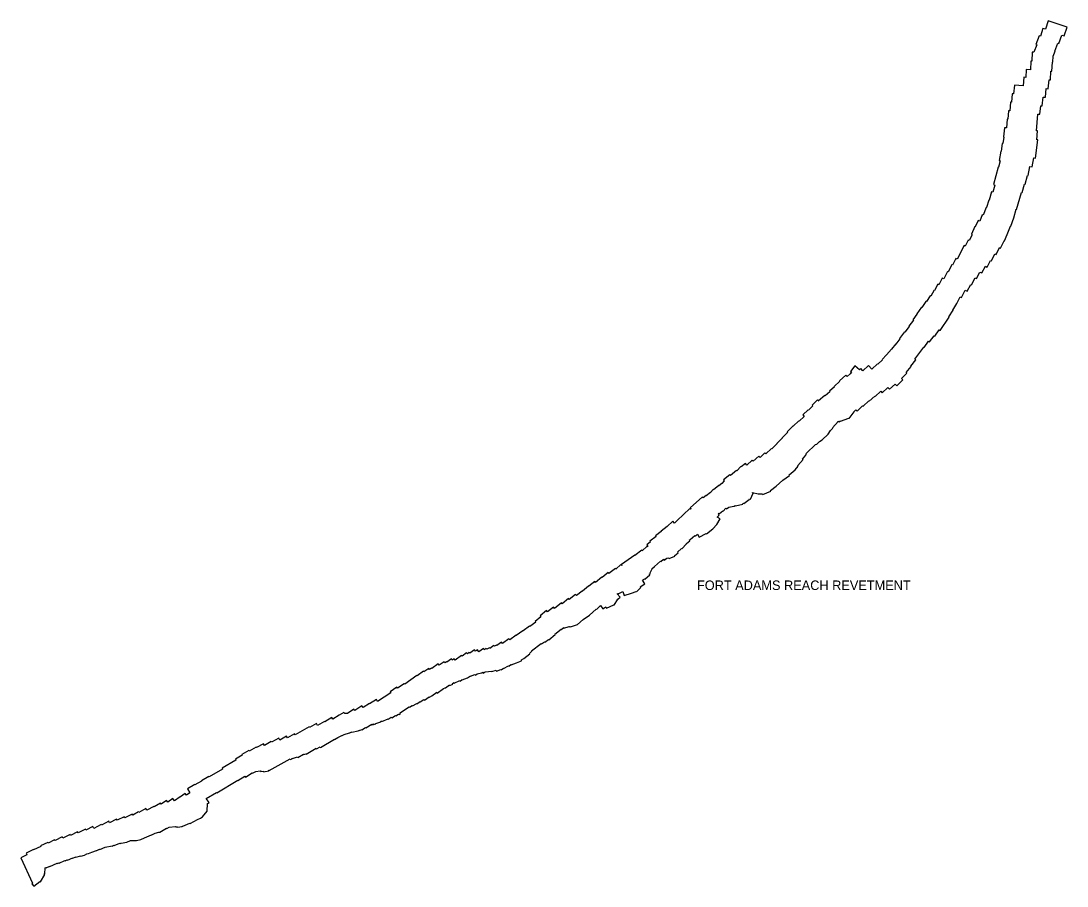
# Model space of a CAD drawing. Extents: x 2650582 to 3923188, y 277893 to 989177.
# Drawn here: x 3192684 to 3210259, y 910761 to 925302 of the extents above; entities that cross this region are included whole.
import ezdxf

# ---------------------------------------------------------------- set-up
doc = ezdxf.new("R2010")
doc.units = 0
doc.layers.add('Level 3', color=7, linetype='Continuous')

msp = doc.modelspace()

# ---------------------------------------------------------------- linework, layer by layer
at = {"layer": 'Level 3'}
for points in [[(3209762, 923454), (3209745, 923456), (3209768, 923736), (3209803, 923733), (3209816, 923877), (3209843, 923874), (3209855, 924023), (3209896, 924019), (3209910, 924165), (3209943, 924162), (3209956, 924314), (3209981, 924314), (3209987, 924459), (3210005, 924459), (3210012, 924608), (3210021, 924609), (3210025, 924708), (3210060, 924792), (3210055, 924794), (3210106, 924929), (3210123, 924923), (3210170, 925063), (3210212, 925050), (3210259, 925198), (3209939, 925302), (3209894, 925161), (3209853, 925174), (3209810, 925045), (3209792, 925052), (3209736, 924907), (3209749, 924901), (3209700, 924776), (3209674, 924776), (3209668, 924627), (3209650, 924628), (3209644, 924482), (3209572, 924483), (3209566, 924353), (3209535, 924355), (3209524, 924209), (3209373, 924222), (3209361, 924075), (3209334, 924077), (3209323, 923934), (3209308, 923935), (3209296, 923791), (3209274, 923793)], [(3209274, 923793), (3209261, 923650), (3209251, 923651), (3209239, 923507), (3209208, 923508), (3209193, 923352), (3209196, 923351), (3209182, 923242), (3209171, 923242), (3209150, 923112), (3209144, 923112), (3209116, 922956), (3209133, 922952), (3209107, 922842), (3209099, 922843), (3209022, 922550), (3209047, 922543), (3209010, 922422), (3208992, 922427), (3208948, 922288), (3208945, 922289), (3208906, 922164), (3208897, 922167), (3208850, 922035), (3208833, 922041), (3208792, 921937), (3208764, 921947), (3208717, 921843), (3208712, 921845), (3208652, 921716), (3208665, 921709), (3208616, 921609), (3208596, 921618), (3208548, 921518), (3208530, 921528), (3208410, 921300), (3208393, 921307), (3208336, 921195), (3208323, 921201), (3208262, 921085), (3208257, 921087), (3208251, 921090), (3208186, 920966)], [(3208548, 920774), (3208578, 920758), (3208640, 920874), (3208653, 920867), (3208714, 920983), (3208737, 920972), (3208795, 921081), (3208826, 921066), (3208887, 921179), (3208914, 921166), (3208973, 921278), (3208992, 921270), (3209048, 921385), (3209068, 921376), (3209125, 921493), (3209142, 921485), (3209200, 921607), (3209207, 921604), (3209253, 921711), (3209307, 921853), (3209313, 921851), (3209367, 921994), (3209365, 921994), (3209406, 922136), (3209408, 922135), (3209492, 922421), (3209504, 922418), (3209542, 922560), (3209555, 922557), (3209593, 922706), (3209603, 922704), (3209636, 922853), (3209671, 922848), (3209701, 923000), (3209730, 922995), (3209768, 923302), (3209749, 923306), (3209762, 923454)], [(3208186, 920966), (3208163, 920980), (3208102, 920868), (3208088, 920875), (3208034, 920773), (3208027, 920777), (3207968, 920676), (3207959, 920682), (3207897, 920585), (3207889, 920589), (3207818, 920486), (3207812, 920490), (3207733, 920377), (3207736, 920375), (3207668, 920279), (3207679, 920271), (3207602, 920169), (3207606, 920166), (3207534, 920073), (3207530, 920076), (3207446, 919964), (3207450, 919960), (3207381, 919870), (3207380, 919872), (3207311, 919785), (3207309, 919787), (3207225, 919690), (3207226, 919689), (3207153, 919613), (3207158, 919607), (3207080, 919534), (3207075, 919538), (3206979, 919447), (3206923, 919508), (3206828, 919421), (3206792, 919458), (3206773, 919440), (3206691, 919503), (3206622, 919411), (3206637, 919398), (3206615, 919370), (3206566, 919324), (3206542, 919348), (3206438, 919253), (3206444, 919246), (3206346, 919159), (3206351, 919153), (3206268, 919078), (3206276, 919068), (3206195, 919000), (3206188, 919008), (3206081, 918918), (3206088, 918909), (3206067, 918931)], [(3206677, 918734), (3206710, 918764), (3206730, 918745), (3206823, 918834), (3206833, 918825), (3206929, 918915), (3206936, 918909), (3207029, 918995), (3207034, 918990), (3207130, 919078), (3207155, 919051), (3207250, 919138), (3207276, 919111), (3207370, 919198), (3207398, 919170), (3207499, 919269), (3207479, 919290), (3207568, 919382), (3207557, 919394), (3207642, 919493), (3207633, 919499), (3207717, 919606), (3207701, 919617), (3207850, 919819), (3207856, 919815), (3207931, 919919), (3207947, 919908), (3208025, 920010), (3208035, 920003), (3208111, 920109), (3208127, 920101), (3208280, 920325), (3208275, 920328), (3208347, 920440), (3208342, 920443), (3208406, 920554), (3208408, 920553), (3208464, 920662), (3208487, 920651), (3208548, 920774)], [(3206067, 918931), (3205978, 918845), (3205990, 918832), (3205915, 918760), (3205910, 918765), (3205821, 918679), (3205843, 918656), (3205757, 918573), (3205750, 918580), (3205656, 918490), (3205654, 918491), (3205554, 918394), (3205564, 918384), (3205470, 918294), (3205475, 918289), (3205382, 918198), (3205385, 918194), (3205299, 918111), (3205292, 918118), (3205199, 918028), (3205184, 918042), (3205103, 917964), (3205083, 917985), (3204985, 917900), (3204970, 917917), (3204878, 917837), (3204856, 917865), (3204784, 917806)], [(3204972, 917374), (3205068, 917356), (3205145, 917351), (3205147, 917345), (3205280, 917401), (3205279, 917409), (3205373, 917482), (3205486, 917581), (3205595, 917664), (3205589, 917673), (3205691, 917758), (3205742, 917821), (3205735, 917827), (3205824, 917933), (3205817, 917939), (3205872, 918004), (3205882, 918036), (3206035, 918185), (3206053, 918191), (3206098, 918235), (3206144, 918262), (3206246, 918356), (3206243, 918359), (3206283, 918419), (3206324, 918460), (3206321, 918463), (3206414, 918567), (3206415, 918575), (3206427, 918562), (3206452, 918583), (3206455, 918577), (3206590, 918627), (3206601, 918620), (3206680, 918732), (3206677, 918734)], [(3204784, 917806), (3204777, 917812), (3204713, 917741), (3204708, 917747), (3204605, 917659), (3204593, 917674), (3204486, 917589), (3204499, 917571), (3204460, 917527), (3204410, 917488), (3204406, 917493), (3204317, 917421), (3204313, 917424), (3204269, 917375), (3204198, 917321), (3204195, 917326), (3204143, 917285), (3204129, 917300), (3204034, 917211), (3204031, 917215), (3203928, 917119), (3203942, 917105), (3203931, 917094), (3203919, 917105), (3203711, 916903), (3203683, 916877), (3203664, 916861), (3203636, 916893), (3203538, 916807), (3203438, 916726), (3203441, 916722), (3203345, 916650), (3203356, 916635), (3203252, 916557), (3203260, 916547), (3203197, 916499), (3203218, 916468), (3203213, 916464), (3203202, 916474), (3203120, 916398), (3203116, 916404), (3202999, 916319), (3202995, 916324), (3202772, 916165), (3202781, 916153)], [(3203479, 916257), (3203493, 916237), (3203537, 916270), (3203571, 916279), (3203576, 916268), (3203671, 916305), (3203667, 916318), (3203723, 916364), (3203717, 916372), (3203783, 916434), (3203788, 916430), (3203867, 916514), (3203864, 916516), (3203921, 916566), (3203913, 916574), (3203926, 916587), (3204003, 916654), (3204015, 916640), (3204053, 916674), (3204076, 916628), (3204198, 916686), (3204200, 916683), (3204308, 916766), (3204310, 916765), (3204374, 916836), (3204433, 916932), (3204383, 916963), (3204415, 916993), (3204401, 917009), (3204417, 917028), (3204421, 917025), (3204474, 917070), (3204484, 917063), (3204528, 917114), (3204537, 917102), (3204576, 917130), (3204663, 917148), (3204665, 917146), (3204684, 917160), (3204687, 917150), (3204812, 917181), (3204812, 917186), (3204823, 917195), (3204828, 917190), (3204920, 917256), (3204918, 917259), (3204925, 917269), (3204939, 917263), (3204986, 917362), (3204972, 917371), (3204972, 917374)], [(3201660, 914990), (3201656, 914996), (3201759, 915077), (3201761, 915074), (3201804, 915106), (3201807, 915097), (3201893, 915123), (3201899, 915117), (3201912, 915126), (3201914, 915120), (3202036, 915159), (3202131, 915239), (3202234, 915315), (3202236, 915313), (3202347, 915413), (3202351, 915408), (3202418, 915474), (3202460, 915419), (3202510, 915456), (3202519, 915434), (3202645, 915487), (3202651, 915484), (3202712, 915585), (3202749, 915614), (3202700, 915675), (3202710, 915680), (3202715, 915671), (3202798, 915712), (3202818, 915645), (3202942, 915684), (3202943, 915682), (3203019, 915712), (3203025, 915706), (3203097, 915778), (3203087, 915789), (3203167, 915843), (3203124, 915905), (3203162, 915925), (3203167, 915920), (3203247, 915993), (3203241, 916001), (3203258, 916017), (3203253, 916023), (3203287, 916091), (3203284, 916093), (3203327, 916133), (3203330, 916130), (3203429, 916223), (3203432, 916218), (3203479, 916257)], [(3202781, 916153), (3202778, 916149), (3202762, 916166), (3202679, 916090), (3202671, 916101), (3202563, 916015), (3202550, 916031), (3202447, 915945), (3202443, 915952), (3202339, 915866), (3202326, 915882), (3202222, 915799), (3202220, 915800), (3202117, 915717), (3202113, 915720), (3202018, 915645), (3202003, 915663), (3201895, 915577), (3201883, 915592), (3201774, 915505), (3201763, 915519), (3201648, 915426), (3201629, 915448), (3201532, 915369), (3201514, 915390), (3201407, 915303), (3201418, 915288), (3201323, 915210), (3201332, 915197), (3201231, 915125), (3201228, 915128), (3201119, 915050), (3201116, 915053), (3201006, 914974), (3201003, 914978), (3200895, 914902), (3200883, 914917), (3200775, 914838), (3200758, 914861), (3200679, 914804)], [(3198975, 913628), (3198980, 913622), (3199025, 913653), (3199032, 913643), (3199060, 913663), (3199054, 913672), (3199093, 913700), (3199094, 913698), (3199207, 913772), (3199210, 913767), (3199258, 913796), (3199261, 913790), (3199333, 913827), (3199335, 913824), (3199390, 913861), (3199393, 913857), (3199454, 913894), (3199462, 913883), (3199543, 913941), (3199547, 913935), (3199586, 913957), (3199669, 914018), (3199676, 914006), (3199782, 914084), (3199785, 914080), (3199812, 914093), (3199814, 914091), (3199886, 914142), (3199892, 914131), (3199938, 914157), (3199935, 914164), (3199960, 914181), (3199965, 914171), (3200055, 914216), (3200062, 914206), (3200097, 914231), (3200099, 914227), (3200184, 914263), (3200187, 914260), (3200234, 914294), (3200238, 914288), (3200310, 914319), (3200320, 914305), (3200349, 914326), (3200421, 914343), (3200422, 914341), (3200441, 914355), (3200451, 914341), (3200482, 914363), (3200596, 914374), (3200597, 914367), (3200670, 914389), (3200675, 914375), (3200747, 914399), (3200750, 914395), (3200789, 914425), (3200793, 914419), (3200873, 914465), (3200879, 914457), (3200917, 914485), (3200919, 914479), (3201009, 914511), (3201008, 914512), (3201095, 914548), (3201091, 914561), (3201131, 914584), (3201130, 914588), (3201132, 914586), (3201232, 914663), (3201228, 914668), (3201266, 914709), (3201260, 914714), (3201426, 914840), (3201432, 914832), (3201479, 914866), (3201483, 914861), (3201546, 914908), (3201550, 914902), (3201660, 914990)], [(3200679, 914804), (3200676, 914809), (3200641, 914791), (3200630, 914805), (3200560, 914754), (3200555, 914763), (3200512, 914741), (3200501, 914756), (3200468, 914732), (3200453, 914753), (3200377, 914698), (3200353, 914732), (3200320, 914710), (3200305, 914730), (3200228, 914673), (3200217, 914687), (3200185, 914664), (3200171, 914683), (3200094, 914627), (3200086, 914638), (3199979, 914558), (3199960, 914582), (3199929, 914559), (3199915, 914578), (3199840, 914524), (3199835, 914530), (3199810, 914513), (3199795, 914532), (3199713, 914473), (3199695, 914495), (3199589, 914418), (3199584, 914424), (3199549, 914399), (3199535, 914420), (3199453, 914361), (3199446, 914371), (3199339, 914297), (3199336, 914302), (3199131, 914153), (3199124, 914162), (3199011, 914090), (3199001, 914104), (3198886, 914027), (3198899, 914007), (3198677, 913864)], [(3198677, 913864), (3198655, 913897), (3198542, 913825), (3198538, 913830), (3198431, 913761), (3198411, 913791), (3198293, 913714), (3198279, 913732), (3198168, 913660), (3198123, 913660), (3198109, 913680), (3198031, 913631), (3198028, 913635), (3197925, 913568), (3197906, 913595), (3197788, 913524), (3197786, 913528), (3197667, 913461), (3197648, 913493), (3197533, 913426), (3197526, 913437), (3197292, 913303), (3197282, 913321), (3197163, 913254), (3197147, 913282), (3197032, 913216), (3197014, 913248), (3196895, 913180), (3196889, 913190), (3196776, 913126), (3196760, 913154), (3196642, 913089), (3196637, 913097), (3196519, 913030), (3196513, 913039), (3196395, 912971), (3196402, 912959), (3196286, 912892), (3196294, 912878), (3196062, 912744), (3196072, 912727), (3195848, 912597), (3195843, 912605), (3195715, 912530), (3195718, 912524), (3195608, 912460), (3195604, 912466), (3195482, 912396), (3195519, 912330)], [(3195797, 912230), (3195971, 912334), (3195974, 912329), (3196327, 912540), (3196330, 912537), (3196446, 912606), (3196454, 912593), (3196569, 912662), (3196573, 912656), (3196629, 912686), (3196702, 912696), (3196705, 912691), (3196715, 912696), (3196717, 912686), (3196758, 912694), (3196760, 912683), (3196848, 912700), (3196848, 912708), (3196853, 912708), (3196857, 912701), (3197206, 912901), (3197211, 912891), (3197244, 912910), (3197246, 912905), (3197330, 912932), (3197338, 912922), (3197432, 912976), (3197434, 912971), (3197473, 912985), (3197475, 912980), (3197643, 913077), (3197648, 913068), (3197711, 913099), (3197715, 913092), (3197952, 913228), (3197953, 913225), (3198007, 913256), (3198007, 913257), (3198075, 913294), (3198079, 913289), (3198112, 913309), (3198113, 913307), (3198206, 913339), (3198210, 913334), (3198242, 913354), (3198245, 913347), (3198347, 913368), (3198348, 913372), (3198351, 913369), (3198371, 913382), (3198374, 913375), (3198410, 913390), (3198411, 913388), (3198472, 913424), (3198476, 913418), (3198577, 913480), (3198581, 913471), (3198599, 913477), (3198598, 913482), (3198606, 913487), (3198609, 913479), (3198649, 913490), (3198649, 913494), (3198731, 913522), (3198730, 913527), (3198744, 913536), (3198748, 913527), (3198852, 913569), (3198854, 913566), (3198906, 913602), (3198914, 913590), (3198975, 913628)], [(3195519, 912330), (3195468, 912289), (3195443, 912317), (3195362, 912258), (3195358, 912262), (3195262, 912193), (3195234, 912231), (3195150, 912172), (3195131, 912198), (3195038, 912137), (3195026, 912156), (3194921, 912093), (3194917, 912099), (3194801, 912034), (3194784, 912064), (3194666, 911997), (3194660, 912006), (3194562, 911951), (3194551, 911972), (3194430, 911909), (3194421, 911925), (3194301, 911869), (3194292, 911886), (3194173, 911824), (3194159, 911849), (3194035, 911785), (3194030, 911793), (3193911, 911729), (3193894, 911760), (3193775, 911698), (3193767, 911715), (3193646, 911653), (3193635, 911672), (3193517, 911612), (3193509, 911628), (3193388, 911567), (3193377, 911587), (3193257, 911526), (3193250, 911539), (3193143, 911484), (3193138, 911494), (3193013, 911437), (3193016, 911428), (3192896, 911370), (3192894, 911373), (3192773, 911315)], [(3193091, 911069), (3193105, 911075), (3193107, 911070), (3193169, 911096), (3193172, 911090), (3193294, 911147), (3193297, 911141), (3193322, 911151), (3193324, 911146), (3193424, 911190), (3193426, 911187), (3193461, 911204), (3193464, 911198), (3193555, 911236), (3193557, 911232), (3193605, 911253), (3193606, 911249), (3193692, 911269), (3193693, 911265), (3193750, 911283), (3193791, 911302), (3193820, 911308), (3193873, 911333), (3193875, 911329), (3193955, 911361), (3193957, 911356), (3194006, 911379), (3194008, 911375), (3194100, 911412), (3194214, 911437), (3194216, 911433), (3194248, 911446), (3194249, 911443), (3194345, 911482), (3194349, 911475), (3194369, 911482), (3194461, 911497), (3194526, 911526), (3194624, 911529), (3194624, 911528), (3194697, 911541), (3194762, 911570), (3194760, 911574), (3194880, 911624), (3194882, 911621), (3194937, 911651), (3194998, 911665), (3195018, 911666), (3195132, 911733), (3195135, 911728), (3195177, 911750), (3195283, 911764), (3195285, 911757), (3195313, 911759), (3195314, 911752), (3195394, 911761), (3195394, 911766), (3195405, 911766), (3195524, 911819), (3195526, 911815), (3195652, 911882), (3195653, 911879), (3195699, 911905), (3195732, 911927), (3195815, 912022), (3195821, 912147), (3195845, 912167), (3195797, 912230)], [(3192773, 911315), (3192784, 911292), (3192782, 911291), (3192785, 911284), (3192684, 911238), (3192879, 910810), (3192868, 910801), (3192900, 910761), (3193003, 910839), (3193015, 910830), (3193087, 910954), (3193070, 910964), (3193085, 910964), (3193091, 911069)]]:
    msp.add_lwpolyline(points, dxfattribs=at)

# ---------------------------------------------------------------- texts
msp.add_text('FORT ADAMS REACH REVETMENT', height=160, dxfattribs=at).set_placement((3204042, 915737))

doc.saveas('drawing.dxf')
